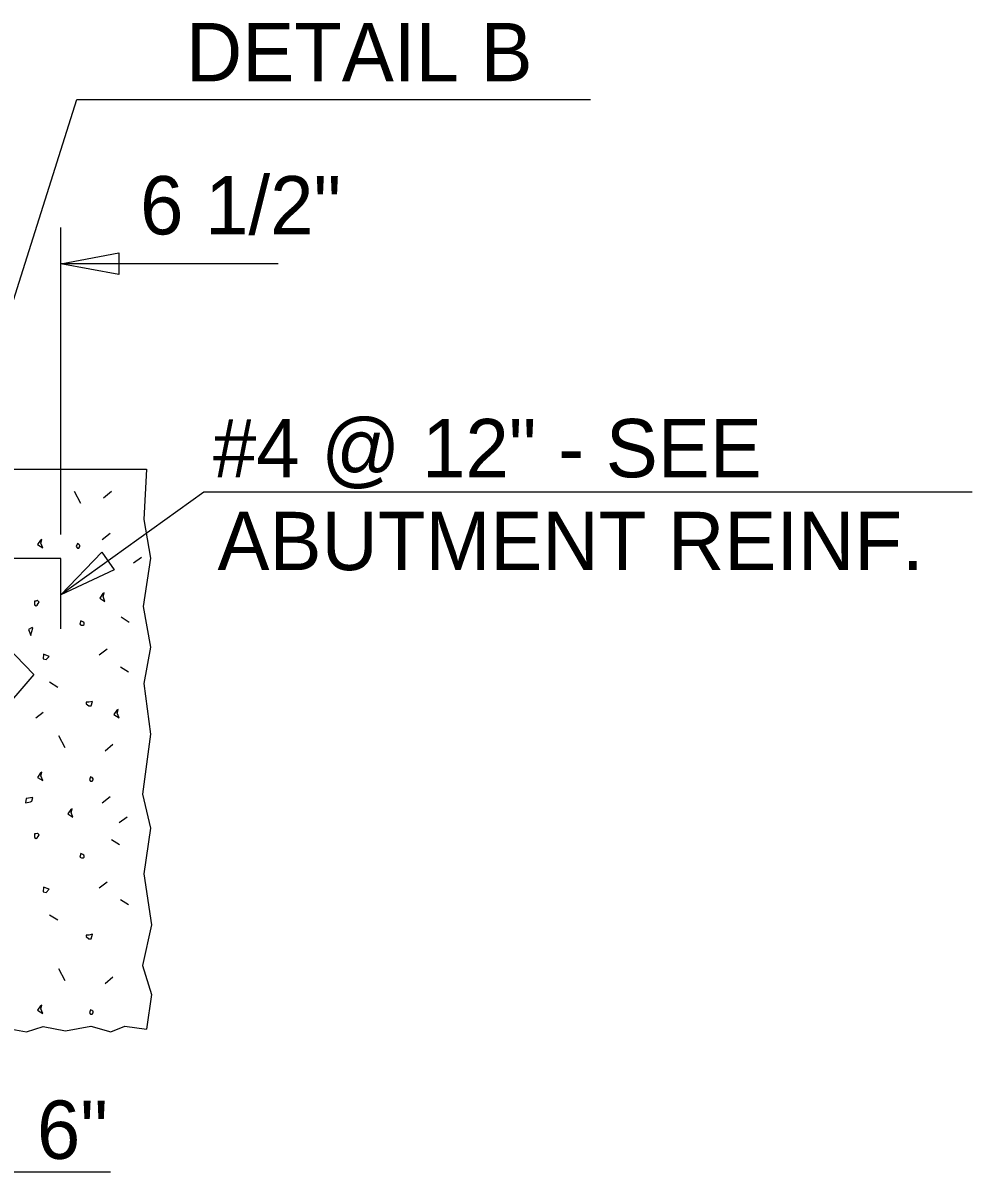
# Model space of a CAD drawing. Extents: x 0 to 68, y 0 to 47.1.
# Drawn here: x 44.28 to 49.37, y 8.69 to 14.85 of the extents above; entities that cross this region are included whole.
import ezdxf

# ---------------------------------------------------------------- set-up
doc = ezdxf.new("R2010")
doc.units = 0
for name, color, linetype in [('BRDG_ANNO_General-Notes', 7, 'Continuous'), ('BRDG_BASE_Obj-Line', 7, 'Continuous'), ('BRDG_BASE_Pattern', 7, 'Continuous'), ('BRDG_BASE_Rebar', 7, 'Continuous')]:
    doc.layers.add(name, color=color, linetype=linetype)

msp = doc.modelspace()

# ---------------------------------------------------------------- linework, layer by layer
at = {"layer": 'BRDG_ANNO_General-Notes'}
for p, q in [((44.0227, 12.6992), (44.5731, 14.4379)), ((44.5731, 14.4379), (47.3261, 14.4379)), ((44.4879, 12.1079), (44.4879, 13.7526)), ((44.4879, 13.5578), (44.7979, 13.6159)), ((44.7979, 13.6159), (44.7979, 13.4997)), ((45.6516, 13.5578), (44.4879, 13.5578)), ((44.7979, 13.4997), (44.4879, 13.5578)), ((45.253, 12.3334), (44.4879, 11.785)), ((49.37, 12.3334), (45.253, 12.3334)), ((44.4879, 11.785), (44.706, 12.0129)), ((44.706, 12.0129), (44.7737, 11.9184)), ((44.7737, 11.9184), (44.4879, 11.785)), ((43.9462, 11.7665), (44.3426, 11.3578)), ((44.3426, 11.3578), (42.3051, 8.9871)), ((44.7528, 8.6921), (43.9462, 8.6921))]:
    msp.add_line(p, q, dxfattribs=at)
at = {"layer": 'BRDG_BASE_Obj-Line'}
msp.add_line((43.9462, 12.4579), (44.9462, 12.4579), dxfattribs=at)
for points in [[(44.9462, 12.4579), (44.9315, 12.1872), (44.9684, 11.9805), (44.9278, 11.7221), (44.9684, 11.5032), (44.9315, 11.3088), (44.9684, 11.0381), (44.9241, 10.7158), (44.9684, 10.5337), (44.9315, 10.2901), (44.9721, 10.0169), (44.9241, 9.798), (44.9721, 9.6429), (44.9462, 9.4579)], [(43.4462, 9.4579), (43.5791, 9.448), (43.6808, 9.4726), (43.808, 9.4464), (43.9154, 9.4726), (44.0114, 9.448), (44.1443, 9.4726), (44.3033, 9.4431), (44.3928, 9.4726), (44.5125, 9.448), (44.647, 9.4743), (44.7545, 9.4431), (44.8307, 9.4743), (44.9462, 9.4579)]]:
    msp.add_lwpolyline(points, dxfattribs=at)
at = {"layer": 'BRDG_BASE_Pattern'}
for p, q in [((44.5588, 12.3395), (44.5929, 12.2745)), ((44.7581, 12.3375), (44.7161, 12.3021)), ((44.7512, 12.1123), (44.708, 12.0789)), ((44.9201, 11.9846), (44.8766, 11.9533)), ((44.8095, 11.6655), (44.8528, 11.638)), ((44.7355, 11.4925), (44.6922, 11.4611)), ((44.807, 11.3994), (44.8503, 11.3717)), ((44.4271, 11.3174), (44.4706, 11.2897)), ((44.3916, 11.154), (44.3529, 11.124)), ((44.4744, 11.0305), (44.5085, 10.9657)), ((44.7658, 10.9828), (44.7238, 10.9473)), ((44.7512, 10.7012), (44.708, 10.6678)), ((44.8431, 10.5938), (44.7998, 10.5622)), ((44.7578, 10.4742), (44.8011, 10.4465)), ((44.7355, 10.2452), (44.6922, 10.2136)), ((44.807, 10.1521), (44.8503, 10.1244)), ((44.4271, 10.0701), (44.4706, 10.0424)), ((44.4744, 9.7832), (44.5085, 9.7182)), ((44.7658, 9.7354), (44.7238, 9.6999))]:
    msp.add_line(p, q, dxfattribs=at)
for points in [[(44.3779, 12.0771), (44.3623, 12.0535), (44.3897, 12.0365), (44.3799, 12.0615), (44.3859, 12.0812)], [(44.5755, 12.0584), (44.569, 12.0426), (44.5755, 12.0346), (44.5833, 12.0346), (44.5886, 12.0426), (44.5886, 12.0504), (44.5872, 12.0504), (44.5833, 12.0543)], [(44.7113, 11.7906), (44.6955, 11.767), (44.7232, 11.7494), (44.714, 11.775), (44.7193, 11.7947)], [(44.3459, 11.7511), (44.3459, 11.7314), (44.3557, 11.7255), (44.3596, 11.7293), (44.3656, 11.7373), (44.3713, 11.7452), (44.3656, 11.7511), (44.3615, 11.7531), (44.3596, 11.7531), (44.3537, 11.7511)], [(44.5944, 11.6455), (44.5893, 11.627), (44.5971, 11.6219), (44.6063, 11.6219), (44.6116, 11.6258), (44.6116, 11.6323), (44.6102, 11.6374), (44.6051, 11.6402)], [(44.3136, 11.598), (44.3255, 11.5667), (44.3255, 11.5705), (44.3373, 11.606), (44.3333, 11.6099)], [(44.3943, 11.4663), (44.3924, 11.4415), (44.4082, 11.4373), (44.4238, 11.4546)], [(44.6379, 11.2091), (44.6221, 11.2091), (44.6221, 11.2011), (44.6379, 11.1894), (44.6495, 11.1894), (44.6576, 11.213)], [(44.7871, 11.1665), (44.7714, 11.1429), (44.7989, 11.1251), (44.7896, 11.1507), (44.7949, 11.1704)], [(44.3779, 10.8298), (44.3623, 10.8062), (44.3897, 10.7892), (44.3799, 10.814), (44.3859, 10.8337)], [(44.6469, 10.8089), (44.6404, 10.7931), (44.6469, 10.7853), (44.6549, 10.7853), (44.66, 10.7931), (44.66, 10.8009), (44.6588, 10.8009), (44.6549, 10.8049)], [(44.3012, 10.694), (44.2973, 10.6705), (44.3247, 10.6756), (44.3313, 10.6789), (44.3367, 10.6992)], [(44.5398, 10.6344), (44.5241, 10.6108), (44.5518, 10.5932), (44.5426, 10.6188), (44.5477, 10.6385)], [(44.3459, 10.5038), (44.3459, 10.4841), (44.3557, 10.4781), (44.3596, 10.482), (44.3656, 10.49), (44.3713, 10.4978), (44.3656, 10.5038), (44.3615, 10.5056), (44.3596, 10.5056), (44.3537, 10.5038)], [(44.5944, 10.3981), (44.5893, 10.3797), (44.5971, 10.3744), (44.6063, 10.3744), (44.6116, 10.3785), (44.6116, 10.385), (44.6102, 10.3902), (44.6051, 10.3928)], [(44.3943, 10.2189), (44.3924, 10.1939), (44.4082, 10.19), (44.4238, 10.207)], [(44.6379, 9.9618), (44.6221, 9.9618), (44.6221, 9.9538), (44.6379, 9.9421), (44.6495, 9.9421), (44.6576, 9.9657)], [(44.3779, 9.5824), (44.3623, 9.5589), (44.3897, 9.5418), (44.3799, 9.5667), (44.3859, 9.5864)], [(44.6469, 9.5615), (44.6404, 9.5457), (44.6469, 9.5378), (44.6549, 9.5378), (44.66, 9.5457), (44.66, 9.5535), (44.6588, 9.5535), (44.6549, 9.5574)]]:
    msp.add_lwpolyline(points, close=True, dxfattribs=at)
at = {"layer": 'BRDG_BASE_Rebar'}
for p, q in [((44.4879, 11.9789), (42.962, 11.9789)), ((44.4879, 11.6016), (44.4879, 11.9789))]:
    msp.add_line(p, q, dxfattribs=at)

# ---------------------------------------------------------------- texts
at = {"layer": 'BRDG_ANNO_General-Notes'}
for s, p in [('DETAIL B', (45.1571, 14.5353)), ('6 1/2"', (44.9117, 13.7151)), ('#4 @ 12" - SEE', (45.3017, 12.4139)), ('ABUTMENT REINF.', (45.3265, 11.9165)), ('6"', (44.3589, 8.7627))]:
    msp.add_text(s, height=0.3125, dxfattribs=at).set_placement(p)

doc.saveas('drawing.dxf')
